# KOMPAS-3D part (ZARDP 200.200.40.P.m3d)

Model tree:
1. Поверхность без истории:1
2. Поверхность без истории:2
3. Поверхность без истории:3
4. Поверхность без истории:4
5. Поверхность без истории:5
6. Поверхность без истории:6
7. Поверхность без истории:7
8. Поверхность без истории:8
9. Поверхность без истории:9
10. Поверхность без истории:10
11. Поверхность без истории:11
12. Поверхность без истории:12
13. Поверхность без истории:13
14. Поверхность без истории:14
15. Поверхность без истории:15
16. Поверхность без истории:16
17. Поверхность без истории:17
18. Поверхность без истории:18
19. Поверхность без истории:19
20. Поверхность без истории:20
21. Поверхность без истории:21
22. Поверхность без истории:22
23. Поверхность без истории:23
24. Поверхность без истории:24
25. Поверхность без истории:25
26. Поверхность без истории:26
27. Поверхность без истории:27
28. Поверхность без истории:28
29. Поверхность без истории:29
30. Поверхность без истории:30
31. Поверхность без истории:31
32. Поверхность без истории:32
33. Поверхность без истории:33
34. Поверхность без истории:34
35. Поверхность без истории:35
36. Поверхность без истории:36
37. Поверхность без истории:37
38. Поверхность без истории:38
39. Поверхность без истории:39
40. Поверхность без истории:40
41. Поверхность без истории:41
42. Поверхность без истории:42
43. Поверхность без истории:43
44. Поверхность без истории:44
45. Поверхность без истории:45
46. Поверхность без истории:46
47. Поверхность без истории:47
48. Поверхность без истории:48
49. Поверхность без истории:49
50. Поверхность без истории:50
51. Поверхность без истории:51
52. Поверхность без истории:52
53. Поверхность без истории:53
54. Поверхность без истории:54
55. Поверхность без истории:55
56. Поверхность без истории:56
57. Поверхность без истории:57
58. Поверхность без истории:58
59. Поверхность без истории:59
60. Поверхность без истории:60
61. Поверхность без истории:61
62. Поверхность без истории:62
63. Поверхность без истории:63
64. Поверхность без истории:64
65. Поверхность без истории:65
66. Поверхность без истории:66
67. Поверхность без истории:67
68. Поверхность без истории:68
69. Поверхность без истории:69
70. Поверхность без истории:70
71. Поверхность без истории:71
72. Поверхность без истории:72
73. Поверхность без истории:73
74. Поверхность без истории:74
75. Поверхность без истории:75
76. Поверхность без истории:76
77. Поверхность без истории:77
78. Поверхность без истории:78
79. Поверхность без истории:79
80. Поверхность без истории:80
81. Поверхность без истории:81
82. Поверхность без истории:82
83. Поверхность без истории:83
84. Поверхность без истории:84
85. Поверхность без истории:85
86. Поверхность без истории:86
87. Поверхность без истории:87
88. Поверхность без истории:88
89. Поверхность без истории:89
90. Поверхность без истории:90
91. Поверхность без истории:91
92. Поверхность без истории:92
93. Поверхность без истории:93
94. Поверхность без истории:94
95. Поверхность без истории:95
96. Поверхность без истории:96
97. Поверхность без истории:97
98. Поверхность без истории:98
99. Поверхность без истории:99
100. Поверхность без истории:100
101. Поверхность без истории:101
102. Поверхность без истории:102
103. Поверхность без истории:103
104. Поверхность без истории:104
105. Поверхность без истории:105
106. Поверхность без истории:106
107. Поверхность без истории:107
108. Поверхность без истории:108
109. Поверхность без истории:109
110. Поверхность без истории:110
111. Поверхность без истории:111

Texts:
  ЗАРДП 200.200.40-ХХ.Р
